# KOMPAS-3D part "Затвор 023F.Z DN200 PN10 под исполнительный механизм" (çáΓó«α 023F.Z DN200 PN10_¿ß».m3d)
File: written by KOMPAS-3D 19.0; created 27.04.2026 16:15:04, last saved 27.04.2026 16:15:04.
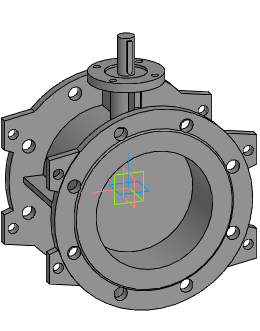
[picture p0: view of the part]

Document properties: Автор: Евгений; Полное имя файла: Z:\3.Личные\kachalov\3d для проектировщиков\1.7 Тип 023F.Z Затвор дисковый поворотный фланцевый с двумя эксцентриками\Затвор 023F.Z DN200-DN1600_исп\_stp_Затвор 023F.Z DN200-DN1600_исп\Затвор 023F.Z DN200 PN10_исп.m3d

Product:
- Part/product: Затвор 023F.Z DN200 PN10 под исполнительный механизм

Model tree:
1. Операция без истории:1  (labels: Затвор 023F.Z DN200 PN10 под исполнительный механизм)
